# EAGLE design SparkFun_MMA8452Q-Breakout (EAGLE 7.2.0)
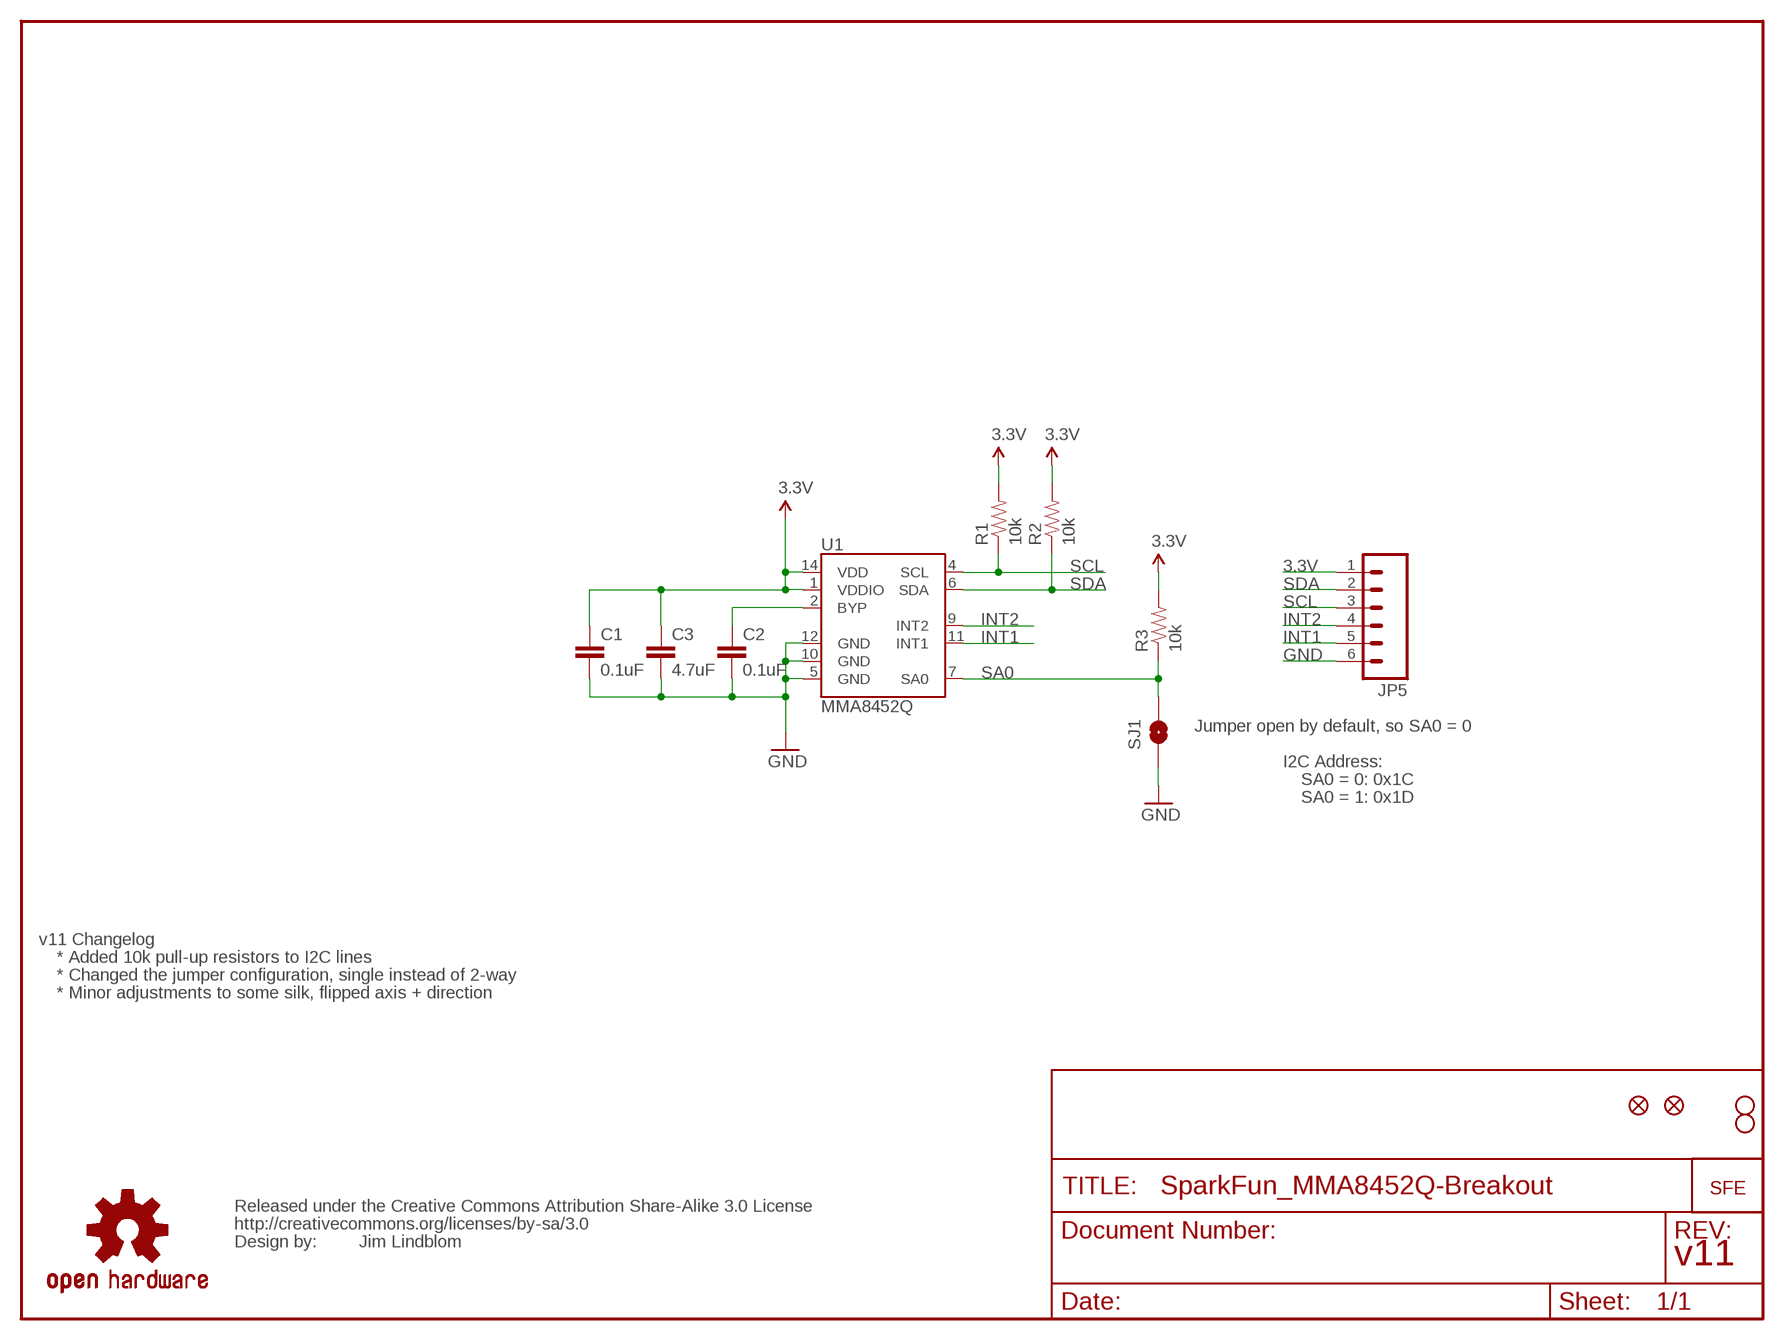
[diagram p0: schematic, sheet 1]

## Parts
C1  0.1uF  CAP0402-CAP  [0402-CAP]
C2  0.1uF  CAP0402-CAP  [0402-CAP]
C3  4.7uF  CAP0402-CAP  [0402-CAP]
JP1  LOGO-SFESK  [SFE-LOGO-FLAME]
JP2  FIDUCIALUFIDUCIAL  [MICRO-FIDUCIAL]
JP3  STAND-OFF  [STAND-OFF]
JP4  STAND-OFF  [STAND-OFF]
JP5  M06SIP  [1X06]
JP6  FIDUCIALUFIDUCIAL  [MICRO-FIDUCIAL]
R1  10k  RESISTOR0402-RES  [0402-RES]
R2  10k  RESISTOR0402-RES  [0402-RES]
R3  10k  RESISTOR0402-RES  [0402-RES]
SJ1  SOLDERJUMPERNO  [SJ_2S-NO]
U1  MMA8452Q  [QFN-16_0.5MM]
U$1  OSHW-LOGOS  [OSHW-LOGO-S]
U$2  CREATIVE_COMMONS  [CREATIVE_COMMONS]

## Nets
3.3V: C1.1 C3.1 JP5.1 R1.2 R2.2 R3.2 U1.1(VDDIO) U1.14(VDD)
BYP: C2.1 U1.2(BYP)
GND: C1.2 C2.2 C3.2 JP5.6 SJ1.1 U1.5(GND) U1.10(GND) U1.12(GND)
INT1: JP5.5 U1.11(INT1)
INT2: JP5.4 U1.9(INT2)
SA0: R3.1 SJ1.2 U1.7(SA0)
SCL: JP5.3 R1.1 U1.4(SCL)
SDA: JP5.2 R2.1 U1.6(SDA)

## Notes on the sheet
- Jumper open by default, so SA0 = 0
- I2C Address:
- SA0 = 0: 0x1C
- SA0 = 1: 0x1D
- v11 Changelog
- * Added 10k pull-up resistors to I2C lines
- * Changed the jumper configuration, single instead of 2-way
- * Minor adjustments to some silk, flipped axis + direction
- Jim Lindblom
- v11

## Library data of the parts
C1-C3 = SparkFun:CAP: Capacitor
JP1 = SparkFun:LOGO-SFE: Spark Fun Electronics PCB Logo
JP2 JP6 = SparkFun:FIDUCIAL: Fiducial Alignment Points
JP3 JP4 = SparkFun:STAND-OFF: Stand Off
JP5 = SparkFun:M06: Header 6 Standard 6-pin 0.1" header. Use with straight break away headers (SKU : PRT-00116), right angle break away headers (PRT-00553), swiss pins (PRT-00743), machine pins (PRT-00117), and female headers (PRT-00115). Molex polarized connector foot print use with SKU : PRT-08094 with associated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
R1-R3 = SparkFun:RESISTOR: Resistor
SJ1 = SparkFun:SOLDERJUMPER: Solder Jumper
U1 = SparkFun:MMA8452Q: MMA8452Q 3-Axis, 12/8-bit Digital Accelerometer Supply Voltage: 1.6-3.6V Range: +/- 2g, 4g, 8g Interface: I2C, 12-bit and 8-bit ODR: 1.56 Hz - 800 Hz Package: QFN-16 http://cache.freescale.com/files/sensors/doc/data_sheet/MMA8452Q.pdf
U$1 = SparkFun:OSHW-LOGO: Open Source Hardware Logo This logo indicates the piece of hardware it is found on incorporates a OSHW license and/or adheres to the definition of open source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
U$2 = SparkFun:CREATIVE_COMMONS

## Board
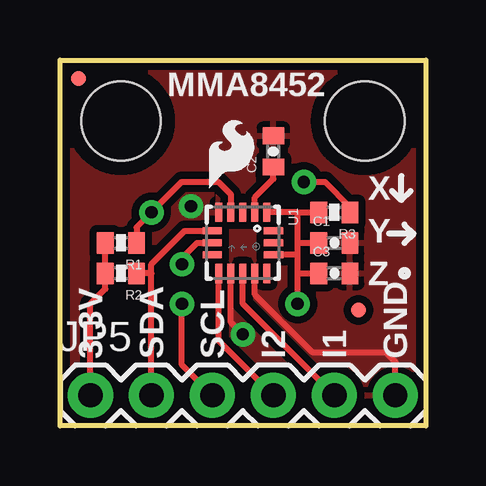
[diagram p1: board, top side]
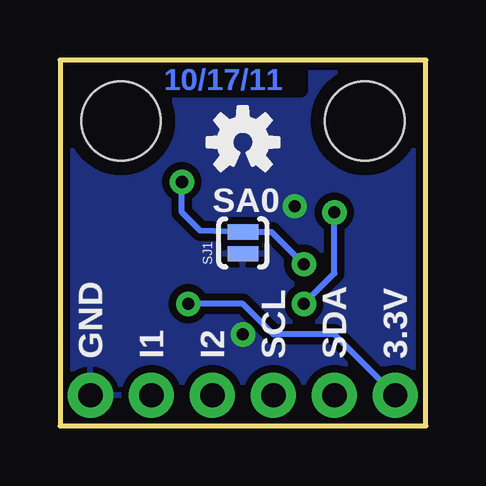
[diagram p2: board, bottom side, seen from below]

Size 15.24 x 15.24 mm. Coordinates in mm from the lower left corner, seen from the top.
Outline: 0,0 0,15.24 15.24,15.24 15.24,0 0,0
Copper layers (1*16): Top 0.035mm / dielectric 1.5mm / Bottom 0.035mm
Design rules "SparkFun": minimum track width 8mil, minimum drill 20mil, track to track 8mil, track to pad 8mil, pad to pad 8mil, via to via 8mil, smd to smd 8mil, copper to edge 8mil, drill to drill 8mil, minimum pad ring 12mil, minimum via ring 10mil, stop-mask expansion 4mil, vias tented up to drill 20mil, thermal gap 10mil

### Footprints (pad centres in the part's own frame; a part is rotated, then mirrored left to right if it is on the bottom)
0402-CAP = smd 0.7 x 0.9: 1 -0.65,0; 2 0.65,0
MICRO-FIDUCIAL = smd 0.635 x 0.635: 1 0,0
STAND-OFF = hole 3.302: 0,0
1X06 = drill 1.016 pad 1.88 round: 1 0,0; 2 2.54,0; 3 5.08,0; 4 7.62,0; 5 10.16,0; 6 12.7,0
0402-RES = smd 0.7 x 0.9: 1 -0.65,0; 2 0.65,0
SJ_2S-NO = smd 0.635 x 1.27: 1 -0.45,0; 2 0.45,0
QFN-16_0.5MM = smd 0.8 x 0.3: 1 -1.275,1; 2 -1.275,0.5; 3 -1.275,0; 4 -1.275,-0.5; 5 -1.275,-1; 9 1.275,-1; 10 1.275,-0.5; 11 1.275,0; 12 1.275,0.5; 13 1.275,1 | smd 0.3 x 0.8: 6 -0.5,-1.275; 7 0,-1.275; 8 0.5,-1.275; 14 0.5,1.275; 15 0,1.275; 16 -0.5,1.275

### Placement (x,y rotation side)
C1  11.43,7.62 0 top
C2  8.89,11.43 90 top
C3  11.43,6.35 0 top
JP1  6.22,9.91 0 top
JP2  12.45,4.83 0 top
JP3  2.54,12.7 0 top
JP4  12.7,12.7 0 top
JP5  1.27,1.27 0 top
JP6  0.76,14.48 0 top
R1  2.54,7.62 180 top
R2  2.54,6.35 180 top
R3  11.43,8.89 180 top
SJ1  7.62,7.62 90 bottom
U1  7.62,7.62 270 top
U$1  7.62,11.81 0 bottom
U$2  not placed on the board

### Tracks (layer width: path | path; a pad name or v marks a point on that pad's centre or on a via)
3.3V  (via drill 0.51)
  Top 0.254: R1.2 R2.2 1.89,5.7 1.27,5.08 JP5.1 | 9.9,7.12 U1.14 | v9.9,5.08 9.9,6.35 | 9.9,6.35 9.9,7.12 | 9.91,8.89 U1.1 | 9.91,8.89 R3.2 | 9.9,7.12 9.9,7.62 | 9.9,7.62 9.9,8.89 9.91,8.89 | 9.9,7.62 C1.1 | 9.9,6.35 C3.1
  Bottom 0.254: v9.9,5.08 7.62,5.08 6.35,3.81 3.81,3.81 JP5.1
BYP
  Top 0.254: U1.2 8.12,9.52 8.89,10.29 C2.1
GND  (via drill 0.51)
  Top 0.254: U1.10 7.12,4.31 v7.62,3.81 | U1.12 8.12,5.47 10.54,3.05 13.59,3.05 13.97,2.67 JP5.6
  other vias: 5.46,9.14
  pour Bottom (isolate 0.305): 0,0 0,15.24 15.24,15.24 15.24,0
  pour Top (isolate 0.305): 0,0 0,15.24 15.24,15.24 15.24,0
INT1
  Top 0.254: U1.11 7.62,5.08 JP5.5
INT2
  Top 0.254: U1.9 6.62,3.54 JP5.4
SA0  (via drill 0.51)
  Top 0.254: U1.7 5.71,7.62 5.08,6.99 v5.08,6.73 | R3.1 12.08,9.13 11.05,10.16 v10.16,10.16
  Bottom 0.254: 5.21,6.86 v5.08,6.73 6.42,8.07 SJ1.2 9.4,8.13 10.16,8.89 v10.16,10.16
SCL  (via drill 0.51)
  Top 0.254: U1.4 7.12,9.64 6.6,10.16 5.08,10.16 v3.81,8.89 3.19,8.27 R1.1 | v5.08,5.08 5.08,2.54 JP5.3
  Bottom 0.254: v3.81,8.89 3.81,6.35 v5.08,5.08
SDA
  Top 0.254: 3.81,6.35 R2.1 | JP5.2 3.81,6.35 | U1.6 5.2,8.12 3.81,6.73 3.81,6.35

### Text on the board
Bottom: 10/17/11
tPlace: MMA8452 | X | Y | Z | 3.3V | SDA | SCL | I2 | I1 | GND
bPlace: SA0 | 3.3V | SDA | SCL | I2 | I1 | GND

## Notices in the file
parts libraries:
SparkFun: Released under the Creative Commons Attribution Share-Alike 3.0 License
SparkFun: http://creativecommons.org/licenses/by-sa/3.0
